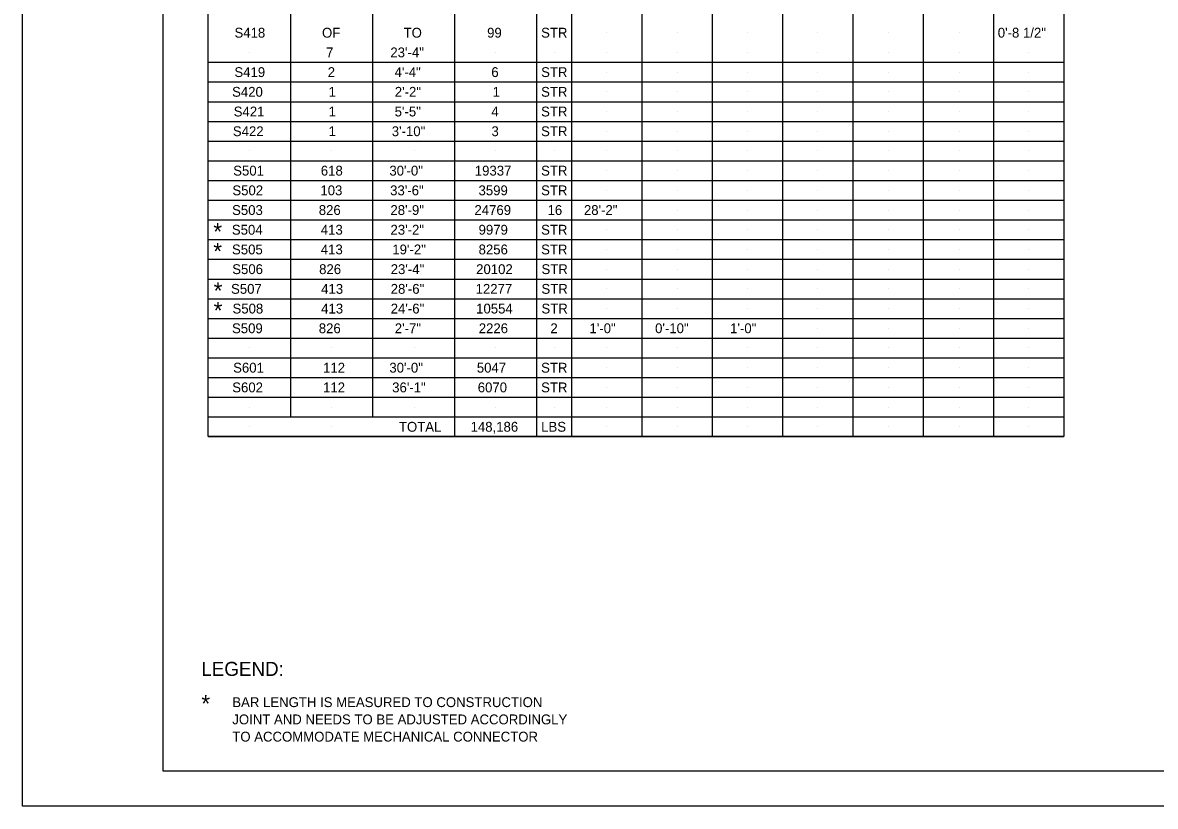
# Model space of a CAD drawing. Extents: x -31.1 to 2.9, y 8.5 to 31.4.
# Drawn here: x -31.13 to -15.02, y 8.48 to 19.62 of the extents above; entities that cross this region are included whole.
import ezdxf

# ---------------------------------------------------------------- set-up
doc = ezdxf.new("R2010")
doc.units = 0
for name, color, linetype in [('BR_P_Gen_Text', 7, 'Continuous'), ('Default', 7, 'Continuous'), ('SC_Scratch1', 7, 'Continuous')]:
    doc.layers.add(name, color=color, linetype=linetype)

msp = doc.modelspace()

# ---------------------------------------------------------------- linework, layer by layer
at = {"layer": 'BR_P_Gen_Text'}
for p, q in [((-16.32, 29.627), (-16.32, 13.737)), ((-27.32, 28.577), (-27.32, 14.017)), ((-26.153, 28.577), (-26.153, 14.017)), ((-24.987, 28.577), (-24.987, 13.737)), ((-23.82, 28.577), (-23.82, 13.737)), ((-23.32, 28.577), (-23.32, 13.737)), ((-22.32, 28.577), (-22.32, 13.737)), ((-21.32, 28.577), (-21.32, 13.737)), ((-20.32, 28.577), (-20.32, 13.737)), ((-19.32, 28.577), (-19.32, 13.737)), ((-18.32, 28.577), (-18.32, 13.737)), ((-17.32, 28.577), (-17.32, 13.737)), ((-28.487, 19.057), (-16.32, 19.057)), ((-28.487, 18.777), (-16.32, 18.777)), ((-28.487, 18.497), (-16.32, 18.497)), ((-28.487, 18.217), (-16.32, 18.217)), ((-28.487, 17.937), (-16.32, 17.937)), ((-28.487, 17.657), (-16.32, 17.657)), ((-28.487, 17.377), (-16.32, 17.377)), ((-28.487, 17.097), (-16.32, 17.097)), ((-28.487, 16.817), (-16.32, 16.817)), ((-28.487, 16.537), (-16.32, 16.537)), ((-28.487, 16.257), (-16.32, 16.257)), ((-28.487, 15.977), (-16.32, 15.977)), ((-28.487, 15.697), (-16.32, 15.697)), ((-28.487, 15.417), (-16.32, 15.417)), ((-28.487, 15.137), (-16.32, 15.137)), ((-28.487, 14.857), (-16.32, 14.857)), ((-28.487, 14.577), (-16.32, 14.577)), ((-28.487, 14.297), (-16.32, 14.297)), ((-28.487, 14.017), (-16.32, 14.017)), ((-16.32, 13.737), (-28.487, 13.737)), ((-28.487, 13.737), (-16.32, 13.737))]:
    msp.add_line(p, q, dxfattribs=at)
for points in [[(-31.128, 30.484), (2.872, 30.484), (2.872, 8.484), (-31.128, 8.484)], [(-29.128, 29.984), (1.372, 29.984), (1.372, 8.984), (-29.128, 8.984)]]:
    msp.add_lwpolyline(points, close=True, dxfattribs=at)
at = {"layer": 'Default'}
msp.add_line((-28.487, 13.737), (-28.487, 29.627), dxfattribs=at)
at = {"layer": 'SC_Scratch1'}
for p, q in [((-27.903, 19.477), (-27.903, 19.477)), ((-26.737, 19.477), (-26.737, 19.477)), ((-25.549, 19.477), (-25.549, 19.477)), ((-24.403, 19.477), (-24.403, 19.477)), ((-23.57, 19.477), (-23.57, 19.477)), ((-22.82, 19.477), (-22.82, 19.477)), ((-21.82, 19.477), (-21.82, 19.477)), ((-20.82, 19.477), (-20.82, 19.477)), ((-19.82, 19.477), (-19.82, 19.477)), ((-18.82, 19.477), (-18.82, 19.477)), ((-17.797, 19.477), (-17.797, 19.477)), ((-16.82, 19.477), (-16.82, 19.477)), ((-27.903, 19.197), (-27.903, 19.197)), ((-26.737, 19.197), (-26.737, 19.197)), ((-25.549, 19.197), (-25.549, 19.197)), ((-24.403, 19.197), (-24.403, 19.197)), ((-23.57, 19.197), (-23.57, 19.197)), ((-22.82, 19.197), (-22.82, 19.197)), ((-21.82, 19.197), (-21.82, 19.197)), ((-20.82, 19.197), (-20.82, 19.197)), ((-19.82, 19.197), (-19.82, 19.197)), ((-18.82, 19.197), (-18.82, 19.197)), ((-17.797, 19.197), (-17.797, 19.197)), ((-16.82, 19.197), (-16.82, 19.197)), ((-27.903, 18.917), (-27.903, 18.917)), ((-26.737, 18.917), (-26.737, 18.917)), ((-25.549, 18.917), (-25.549, 18.917)), ((-24.403, 18.917), (-24.403, 18.917)), ((-23.57, 18.917), (-23.57, 18.917)), ((-22.82, 18.917), (-22.82, 18.917)), ((-21.82, 18.917), (-21.82, 18.917)), ((-20.82, 18.917), (-20.82, 18.917)), ((-19.82, 18.917), (-19.82, 18.917)), ((-18.82, 18.917), (-18.82, 18.917)), ((-17.797, 18.917), (-17.797, 18.917)), ((-16.82, 18.917), (-16.82, 18.917)), ((-27.903, 18.637), (-27.903, 18.637)), ((-26.737, 18.637), (-26.737, 18.637)), ((-25.549, 18.637), (-25.549, 18.637)), ((-24.403, 18.637), (-24.403, 18.637)), ((-23.57, 18.637), (-23.57, 18.637)), ((-22.82, 18.637), (-22.82, 18.637)), ((-21.82, 18.637), (-21.82, 18.637)), ((-20.82, 18.637), (-20.82, 18.637)), ((-19.82, 18.637), (-19.82, 18.637)), ((-18.82, 18.637), (-18.82, 18.637)), ((-17.797, 18.637), (-17.797, 18.637)), ((-16.82, 18.637), (-16.82, 18.637)), ((-27.903, 18.357), (-27.903, 18.357)), ((-26.737, 18.357), (-26.737, 18.357)), ((-25.549, 18.357), (-25.549, 18.357)), ((-24.403, 18.357), (-24.403, 18.357)), ((-23.57, 18.357), (-23.57, 18.357)), ((-22.82, 18.357), (-22.82, 18.357)), ((-21.82, 18.357), (-21.82, 18.357)), ((-20.82, 18.357), (-20.82, 18.357)), ((-19.82, 18.357), (-19.82, 18.357)), ((-18.82, 18.357), (-18.82, 18.357)), ((-17.797, 18.357), (-17.797, 18.357)), ((-16.82, 18.357), (-16.82, 18.357)), ((-27.903, 18.077), (-27.903, 18.077)), ((-26.737, 18.077), (-26.737, 18.077)), ((-25.549, 18.077), (-25.549, 18.077)), ((-24.403, 18.077), (-24.403, 18.077)), ((-23.57, 18.077), (-23.57, 18.077)), ((-22.82, 18.077), (-22.82, 18.077)), ((-21.82, 18.077), (-21.82, 18.077)), ((-20.82, 18.077), (-20.82, 18.077)), ((-19.82, 18.077), (-19.82, 18.077)), ((-18.82, 18.077), (-18.82, 18.077)), ((-17.797, 18.077), (-17.797, 18.077)), ((-16.82, 18.077), (-16.82, 18.077)), ((-27.903, 17.797), (-27.903, 17.797)), ((-26.737, 17.797), (-26.737, 17.797)), ((-25.549, 17.797), (-25.549, 17.797)), ((-24.403, 17.797), (-24.403, 17.797)), ((-23.57, 17.797), (-23.57, 17.797)), ((-22.82, 17.797), (-22.82, 17.797)), ((-21.82, 17.797), (-21.82, 17.797)), ((-20.82, 17.797), (-20.82, 17.797)), ((-19.82, 17.797), (-19.82, 17.797)), ((-18.82, 17.797), (-18.82, 17.797)), ((-17.797, 17.797), (-17.797, 17.797)), ((-16.82, 17.797), (-16.82, 17.797)), ((-27.903, 17.517), (-27.903, 17.517)), ((-26.737, 17.517), (-26.737, 17.517)), ((-25.549, 17.517), (-25.549, 17.517)), ((-24.403, 17.517), (-24.403, 17.517)), ((-23.57, 17.517), (-23.57, 17.517)), ((-22.82, 17.517), (-22.82, 17.517)), ((-21.82, 17.517), (-21.82, 17.517)), ((-20.82, 17.517), (-20.82, 17.517)), ((-19.82, 17.517), (-19.82, 17.517)), ((-18.82, 17.517), (-18.82, 17.517)), ((-17.797, 17.517), (-17.797, 17.517)), ((-16.82, 17.517), (-16.82, 17.517)), ((-27.903, 17.237), (-27.903, 17.237)), ((-26.737, 17.237), (-26.737, 17.237)), ((-25.549, 17.237), (-25.549, 17.237)), ((-24.403, 17.237), (-24.403, 17.237)), ((-23.57, 17.237), (-23.57, 17.237)), ((-22.82, 17.237), (-22.82, 17.237)), ((-21.82, 17.237), (-21.82, 17.237)), ((-20.82, 17.237), (-20.82, 17.237)), ((-19.82, 17.237), (-19.82, 17.237)), ((-18.82, 17.237), (-18.82, 17.237)), ((-17.797, 17.237), (-17.797, 17.237)), ((-16.82, 17.237), (-16.82, 17.237)), ((-27.903, 16.957), (-27.903, 16.957)), ((-26.737, 16.957), (-26.737, 16.957)), ((-25.549, 16.957), (-25.549, 16.957)), ((-24.403, 16.957), (-24.403, 16.957)), ((-23.57, 16.957), (-23.57, 16.957)), ((-22.82, 16.957), (-22.82, 16.957)), ((-21.82, 16.957), (-21.82, 16.957)), ((-20.82, 16.957), (-20.82, 16.957)), ((-19.82, 16.957), (-19.82, 16.957)), ((-18.82, 16.957), (-18.82, 16.957)), ((-17.797, 16.957), (-17.797, 16.957)), ((-16.82, 16.957), (-16.82, 16.957)), ((-27.903, 16.677), (-27.903, 16.677)), ((-26.737, 16.677), (-26.737, 16.677)), ((-25.549, 16.677), (-25.549, 16.677)), ((-24.403, 16.677), (-24.403, 16.677)), ((-23.57, 16.677), (-23.57, 16.677)), ((-22.82, 16.677), (-22.82, 16.677)), ((-21.82, 16.677), (-21.82, 16.677)), ((-20.82, 16.677), (-20.82, 16.677)), ((-19.82, 16.677), (-19.82, 16.677)), ((-18.82, 16.677), (-18.82, 16.677)), ((-17.797, 16.677), (-17.797, 16.677)), ((-16.82, 16.677), (-16.82, 16.677)), ((-27.903, 16.397), (-27.903, 16.397)), ((-26.737, 16.397), (-26.737, 16.397)), ((-25.549, 16.397), (-25.549, 16.397)), ((-24.403, 16.397), (-24.403, 16.397)), ((-23.57, 16.397), (-23.57, 16.397)), ((-22.82, 16.397), (-22.82, 16.397)), ((-21.82, 16.397), (-21.82, 16.397)), ((-20.82, 16.397), (-20.82, 16.397)), ((-19.82, 16.397), (-19.82, 16.397)), ((-18.82, 16.397), (-18.82, 16.397)), ((-17.797, 16.397), (-17.797, 16.397)), ((-16.82, 16.397), (-16.82, 16.397)), ((-27.903, 16.117), (-27.903, 16.117)), ((-26.737, 16.117), (-26.737, 16.117)), ((-25.549, 16.117), (-25.549, 16.117)), ((-24.403, 16.117), (-24.403, 16.117)), ((-23.57, 16.117), (-23.57, 16.117)), ((-22.82, 16.117), (-22.82, 16.117)), ((-21.82, 16.117), (-21.82, 16.117)), ((-20.82, 16.117), (-20.82, 16.117)), ((-19.82, 16.117), (-19.82, 16.117)), ((-18.82, 16.117), (-18.82, 16.117)), ((-17.797, 16.117), (-17.797, 16.117)), ((-16.82, 16.117), (-16.82, 16.117)), ((-27.903, 15.837), (-27.903, 15.837)), ((-26.737, 15.837), (-26.737, 15.837)), ((-25.549, 15.837), (-25.549, 15.837)), ((-24.403, 15.837), (-24.403, 15.837)), ((-23.57, 15.837), (-23.57, 15.837)), ((-22.82, 15.837), (-22.82, 15.837)), ((-21.82, 15.837), (-21.82, 15.837)), ((-20.82, 15.837), (-20.82, 15.837)), ((-19.82, 15.837), (-19.82, 15.837)), ((-18.82, 15.837), (-18.82, 15.837)), ((-17.797, 15.837), (-17.797, 15.837)), ((-16.82, 15.837), (-16.82, 15.837)), ((-27.903, 15.557), (-27.903, 15.557)), ((-26.737, 15.557), (-26.737, 15.557)), ((-25.549, 15.557), (-25.549, 15.557)), ((-24.403, 15.557), (-24.403, 15.557)), ((-23.57, 15.557), (-23.57, 15.557)), ((-22.82, 15.557), (-22.82, 15.557)), ((-21.82, 15.557), (-21.82, 15.557)), ((-20.82, 15.557), (-20.82, 15.557)), ((-19.82, 15.557), (-19.82, 15.557)), ((-18.82, 15.557), (-18.82, 15.557)), ((-17.797, 15.557), (-17.797, 15.557)), ((-16.82, 15.557), (-16.82, 15.557)), ((-27.903, 15.277), (-27.903, 15.277)), ((-26.737, 15.277), (-26.737, 15.277)), ((-25.549, 15.277), (-25.549, 15.277)), ((-24.403, 15.277), (-24.403, 15.277)), ((-23.57, 15.277), (-23.57, 15.277)), ((-22.82, 15.277), (-22.82, 15.277)), ((-21.82, 15.277), (-21.82, 15.277)), ((-20.82, 15.277), (-20.82, 15.277)), ((-19.82, 15.277), (-19.82, 15.277)), ((-18.82, 15.277), (-18.82, 15.277)), ((-17.797, 15.277), (-17.797, 15.277)), ((-16.82, 15.277), (-16.82, 15.277)), ((-27.903, 14.997), (-27.903, 14.997)), ((-26.737, 14.997), (-26.737, 14.997)), ((-25.549, 14.997), (-25.549, 14.997)), ((-24.403, 14.997), (-24.403, 14.997)), ((-23.57, 14.997), (-23.57, 14.997)), ((-22.82, 14.997), (-22.82, 14.997)), ((-21.82, 14.997), (-21.82, 14.997)), ((-20.82, 14.997), (-20.82, 14.997)), ((-19.82, 14.997), (-19.82, 14.997)), ((-18.82, 14.997), (-18.82, 14.997)), ((-17.797, 14.997), (-17.797, 14.997)), ((-16.82, 14.997), (-16.82, 14.997)), ((-27.903, 14.717), (-27.903, 14.717)), ((-26.737, 14.717), (-26.737, 14.717)), ((-25.549, 14.717), (-25.549, 14.717)), ((-24.403, 14.717), (-24.403, 14.717)), ((-23.57, 14.717), (-23.57, 14.717)), ((-22.82, 14.717), (-22.82, 14.717)), ((-21.82, 14.717), (-21.82, 14.717)), ((-20.82, 14.717), (-20.82, 14.717)), ((-19.82, 14.717), (-19.82, 14.717)), ((-18.82, 14.717), (-18.82, 14.717)), ((-17.797, 14.717), (-17.797, 14.717)), ((-16.82, 14.717), (-16.82, 14.717)), ((-27.903, 14.437), (-27.903, 14.437)), ((-26.737, 14.437), (-26.737, 14.437)), ((-25.549, 14.437), (-25.549, 14.437)), ((-24.403, 14.437), (-24.403, 14.437)), ((-23.57, 14.437), (-23.57, 14.437)), ((-22.82, 14.437), (-22.82, 14.437)), ((-21.82, 14.437), (-21.82, 14.437)), ((-20.82, 14.437), (-20.82, 14.437)), ((-19.82, 14.437), (-19.82, 14.437)), ((-18.82, 14.437), (-18.82, 14.437)), ((-17.797, 14.437), (-17.797, 14.437)), ((-16.82, 14.437), (-16.82, 14.437)), ((-27.903, 14.157), (-27.903, 14.157)), ((-26.737, 14.157), (-26.737, 14.157)), ((-25.549, 14.157), (-25.549, 14.157)), ((-24.403, 14.157), (-24.403, 14.157)), ((-23.57, 14.157), (-23.57, 14.157)), ((-22.82, 14.157), (-22.82, 14.157)), ((-21.82, 14.157), (-21.82, 14.157)), ((-20.82, 14.157), (-20.82, 14.157)), ((-19.82, 14.157), (-19.82, 14.157)), ((-18.82, 14.157), (-18.82, 14.157)), ((-17.797, 14.157), (-17.797, 14.157)), ((-16.82, 14.157), (-16.82, 14.157)), ((-27.903, 13.877), (-27.903, 13.877)), ((-26.737, 13.877), (-26.737, 13.877)), ((-25.549, 13.877), (-25.549, 13.877)), ((-24.403, 13.877), (-24.403, 13.877)), ((-23.57, 13.877), (-23.57, 13.877)), ((-22.82, 13.877), (-22.82, 13.877)), ((-21.82, 13.877), (-21.82, 13.877)), ((-20.82, 13.877), (-20.82, 13.877)), ((-19.82, 13.877), (-19.82, 13.877)), ((-18.82, 13.877), (-18.82, 13.877)), ((-17.797, 13.877), (-17.797, 13.877)), ((-16.82, 13.877), (-16.82, 13.877))]:
    msp.add_line(p, q, dxfattribs=at)

# ---------------------------------------------------------------- texts
at = {"layer": 'BR_P_Gen_Text'}
for s, height, p in [('S418', 0.14, (-28.115, 19.407)), ('OF', 0.14, (-26.87, 19.407)), ('TO', 0.14, (-25.71, 19.407)), ('99', 0.14, (-24.522, 19.407)), ('STR', 0.14, (-23.754, 19.407)), ('0\'-8 1/2"', 0.14, (-17.259, 19.407)), ('7', 0.14, (-26.812, 19.127)), ('23\'-4"', 0.14, (-25.898, 19.127)), ('S419', 0.14, (-28.116, 18.847)), ('2', 0.14, (-26.789, 18.847)), ('4\'-4"', 0.14, (-25.838, 18.847)), ('6', 0.14, (-24.462, 18.847)), ('STR', 0.14, (-23.754, 18.847)), ('S420', 0.14, (-28.149, 18.567)), ('1', 0.14, (-26.777, 18.567)), ('2\'-2"', 0.14, (-25.835, 18.567)), ('1', 0.14, (-24.443, 18.567)), ('STR', 0.14, (-23.754, 18.567)), ('S421', 0.14, (-28.126, 18.287)), ('1', 0.14, (-26.777, 18.287)), ('5\'-5"', 0.14, (-25.837, 18.287)), ('4', 0.14, (-24.462, 18.287)), ('STR', 0.14, (-23.754, 18.287)), ('S422', 0.14, (-28.138, 18.007)), ('1', 0.14, (-26.777, 18.007)), ('3\'-10"', 0.14, (-25.878, 18.007)), ('3', 0.14, (-24.46, 18.007)), ('STR', 0.14, (-23.754, 18.007)), ('S501', 0.14, (-28.133, 17.447)), ('618', 0.14, (-26.887, 17.447)), ('30\'-0"', 0.14, (-25.912, 17.447)), ('19337', 0.14, (-24.697, 17.447)), ('STR', 0.14, (-23.754, 17.447)), ('S502', 0.14, (-28.145, 17.167)), ('103', 0.14, (-26.893, 17.167)), ('33\'-6"', 0.14, (-25.901, 17.167)), ('3599', 0.14, (-24.644, 17.167)), ('STR', 0.14, (-23.754, 17.167)), ('S503', 0.14, (-28.149, 16.887)), ('826', 0.14, (-26.916, 16.887)), ('28\'-9"', 0.14, (-25.897, 16.887)), ('24769', 0.14, (-24.702, 16.887)), ('16', 0.14, (-23.662, 16.887)), ('28\'-2"', 0.14, (-23.145, 16.887)), ('*', 0.24, (-28.416, 16.531)), ('S504', 0.14, (-28.152, 16.607)), ('413', 0.14, (-26.887, 16.607)), ('23\'-2"', 0.14, (-25.896, 16.607)), ('9979', 0.14, (-24.643, 16.607)), ('STR', 0.14, (-23.754, 16.607)), ('*', 0.24, (-28.416, 16.251)), ('S505', 0.14, (-28.15, 16.327)), ('413', 0.14, (-26.887, 16.327)), ('19\'-2"', 0.14, (-25.87, 16.327)), ('8256', 0.14, (-24.643, 16.327)), ('STR', 0.14, (-23.754, 16.327)), ('S506', 0.14, (-28.147, 16.047)), ('826', 0.14, (-26.911, 16.047)), ('23\'-4"', 0.14, (-25.893, 16.047)), ('20102', 0.14, (-24.678, 16.047)), ('STR', 0.14, (-23.749, 16.047)), ('*', 0.24, (-28.411, 15.691)), ('S507', 0.14, (-28.164, 15.767)), ('413', 0.14, (-26.882, 15.767)), ('28\'-6"', 0.14, (-25.893, 15.767)), ('12277', 0.14, (-24.686, 15.767)), ('STR', 0.14, (-23.749, 15.767)), ('*', 0.24, (-28.411, 15.411)), ('S508', 0.14, (-28.143, 15.487)), ('413', 0.14, (-26.882, 15.487)), ('24\'-6"', 0.14, (-25.893, 15.487)), ('10554', 0.14, (-24.678, 15.487)), ('STR', 0.14, (-23.749, 15.487)), ('S509', 0.14, (-28.15, 15.207)), ('826', 0.14, (-26.916, 15.207)), ('2\'-7"', 0.14, (-25.835, 15.207)), ('2226', 0.14, (-24.641, 15.207)), ('2', 0.14, (-23.622, 15.207)), ('1\'-0"', 0.14, (-23.066, 15.207)), ('0\'-10"', 0.14, (-22.133, 15.207)), ('1\'-0"', 0.14, (-21.066, 15.207)), ('S601', 0.14, (-28.134, 14.647)), ('112', 0.14, (-26.855, 14.647)), ('30\'-0"', 0.14, (-25.912, 14.647)), ('5047', 0.14, (-24.668, 14.647)), ('STR', 0.14, (-23.754, 14.647)), ('S602', 0.14, (-28.147, 14.367)), ('112', 0.14, (-26.855, 14.367)), ('36\'-1"', 0.14, (-25.872, 14.367)), ('6070', 0.14, (-24.655, 14.367)), ('STR', 0.14, (-23.754, 14.367)), ('TOTAL', 0.14, (-25.776, 13.807)), ('148,186', 0.14, (-24.757, 13.807)), ('LBS', 0.14, (-23.753, 13.807)), ('LEGEND:', 0.2, (-28.587, 10.337)), ('*', 0.24, (-28.586, 9.825)), ('BAR LENGTH IS MEASURED TO CONSTRUCTION', 0.14, (-28.146, 9.894)), ('JOINT AND NEEDS TO BE ADJUSTED ACCORDINGLY', 0.14, (-28.146, 9.649)), ('TO ACCOMMODATE MECHANICAL CONNECTOR', 0.14, (-28.146, 9.404))]:
    msp.add_text(s, height=height, dxfattribs=at).set_placement(p)

doc.saveas('drawing.dxf')
